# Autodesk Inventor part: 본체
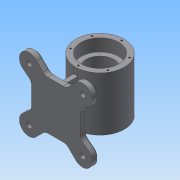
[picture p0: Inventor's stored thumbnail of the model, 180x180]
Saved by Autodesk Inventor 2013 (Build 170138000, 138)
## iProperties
Created: 2018-03
Part Number: 본체
Material: 일반
Document SubType Name: Modeling
Designer: Administrator
Density: 1 g/cm^3
Author: Administrator
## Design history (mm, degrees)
sketch "스케치2"
  geometry: C1 r 45 at (0, 0); 1 further point
  constraints: 1 centre point, 1 coincident
  dimensions: "d42" = 90 diameter of C1
extrude "돌출2" new body sketch "스케치2" stored distance "d44" = 100; taper "d45" = 0 deg
hole "구멍1" diameter "d48" = 70; stored, may be unused: countersink angle "d52" = 90 deg, drill point angle "d54" = 0 deg; dims "d46" = 10, "d47" = 10, "d49" = 6, "d50" = 4, "d51" = 2, "d53" = 23
hole "구멍2" diameter "d57" = 52; stored, may be unused: countersink angle "d61" = 90 deg, drill point angle "d63" = 0 deg; dims "d55" = 10, "d56" = 10, "d58" = 6, "d59" = 4, "d60" = 2, "d62" = 47
hole "구멍3" diameter "d66" = 40; stored, may be unused: countersink angle "d70" = 90 deg, drill point angle "d72" = 0 deg; dims "d64" = 10, "d65" = 10, "d67" = 6, "d68" = 4, "d69" = 2, "d71" = 30
node "작업 평면2"
sketch "스케치4"
  geometry: L1 (0, 0)-(-45, 0); L2 (-45, 0)-(-45, 45); L3 (-45, 45)-(0, 45); L4 (0, 45)-(0, 0); L5 (0, 0)-(-49.497, 49.497); L6 (0, 0)-(70, 0); L7 (-60.483, 35.239)-(-49.871, 27.062); L8 (-35.239, 60.483)-(-23.417, 48.661); L9 (0, 45)-(-14.578, 45); L10 (-45, 0)-(-45, 17.16); A1 r 70 centre (0, 0) between (-49.497, 49.497) and (-60.483, 35.239); A2 r 18 centre (-49.497, 49.497) between (-35.239, 60.483) and (-60.483, 35.239); A3 r 12.5 centre (-57.5, 17.16) between (-45, 17.16) and (-49.871, 27.062); A4 r 12.5 centre (-14.578, 57.5) between (-23.417, 48.661) and (-14.578, 45)
  constraints: 20 end point, 9 point on circle, 6 tangent, 4 centre point, 3 parallel, 2 coincident, 2 horizontal, 2 point on line, 1 collinear, 1 equal length, 1 perpendicular
  dimensions: "d74" = 45 distance of L2.end L3.end; "d75" = 45 distance of L1.end L2.end; "d76" = 140 diameter of A1; "d77" = 135 deg angle of L6 L5; "d78" = 36 diameter of A2; "d79" = 25 diameter of A3; "d80" = 25 diameter of A4
extrude "돌출3" join sketch "스케치4" distance "d81" = 12; taper "d82" = 0 deg
sketch "스케치5"
  geometry: L1 (-45, -82)-(-45, -70) reference; L2 (-45, -70)-(45, -70) reference; L3 (45, -70)-(45, -82) reference; L4 (45, -82)-(-45, -82) reference; L5 (21.342, -39.617)-(24, -70); L6 (-21.342, -39.617)-(-24, -70); L7 (-24, -70)-(0, -70); L8 (0, -70)-(24, -70); C1 r 26 at (0, 0) reference; A1 r 45 centre (0, 0) between (21.342, -39.617) and (-21.342, -39.617) reference; 1 further point
  constraints: 8 end point, 2 point on circle, 2 point on line, 1 collinear, 1 midpoint
  dimensions: "d85" = 24 distance of L6.end L7.end; "d86" = 24 distance of L5.end L7.end; "d87" = 95 deg angle of L5 L2; "d88" = 95 deg angle of L2 L6
extrude "돌출4" join sketch "스케치5" stored distance "d89" = 8; taper "d90" = 0 deg
sketch "스케치6"
  geometry: L1 (35, 27)-(35, 50) reference; L2 (35, 50)-(45, 50) reference; L3 (45, 50)-(45, -50) reference; L4 (45, -50)-(20, -50) reference; L5 (20, -50)-(20, -20) reference; L6 (20, -20)-(26, -20) reference; L7 (26, -20)-(26, 27) reference; L8 (26, 27)-(35, 27) reference; L9 (-82, 45)-(-70, 45) reference; L10 (-70, 45)-(-70, 4) reference; L11 (-70, 4)-(-45, 4) reference; L12 (-45, 4)-(-45, 50) reference; L13 (-45, 50)-(-35, 50) reference; L14 (-35, 50)-(-35, 27) reference; L15 (-35, 27)-(-26, 27) reference; L16 (-26, 27)-(-26, -20) reference; L17 (-26, -20)-(-20, -20) reference; L18 (-20, -20)-(-20, -50) reference; L19 (-20, -50)-(-45, -50) reference; L20 (-45, -50)-(-45, -4) reference; L21 (-45, -4)-(-70, -4) reference; L22 (-70, -4)-(-70, -45) reference; L23 (-70, -45)-(-82, -45) reference; L24 (-82, -45)-(-82, 45) reference; L25 (-70, 4)-(-70, -4); L26 (-70, 0)-(-70, 37); L27 (-70, 0)-(-70, -37); L28 (-70, 37)-(-45, 37); L29 (-70, -37)-(-45, -37); 1 further point
  constraints: 10 end point, 4 point on line, 2 perpendicular, 1 midpoint, 1 parallel
  dimensions: "d93" = 37 distance of L26.start L26.end; "d94" = 37 distance of L26.start L27.end
extrude "돌출5" join sketch "스케치6" stored distance "d95" = 8; taper "d96" = 0 deg
sketch "스케치7"
  geometry: A1 r 45 centre (0, 0) between (4, -44.822) and (-4, -44.822) reference; 1 further point
  constraints: 1 vertical alignment
  dimensions: "d97" = 40 distance of A1.centre point (0, 40)
hole "구멍4" sketch "스케치7" at (0, 40) diameter "d98" = 3.242; stored, may be unused: countersink angle "d102" = 90 deg, drill point angle "d104" = 118 deg; dims "d99" = 9, "d100" = 4, "d101" = 2, "d103" = 11
node "작업 평면3"
sketch "스케치8"
  geometry: L1 (-12.5, -12.5)-(12.5, -12.5); L2 (12.5, -12.5)-(12.5, 12.5); L3 (12.5, 12.5)-(-12.5, 12.5); L4 (-12.5, 12.5)-(-12.5, -12.5); L5 (-12.5, -12.5)-(12.5, 12.5); L6 (12.5, -12.5)-(-12.5, 12.5); 1 further point
  constraints: 12 end point, 2 midpoint, 2 parallel, 1 horizontal, 1 perpendicular
  dimensions: "d108" = 25 distance of L3.end L2.end; "d109" = 25 distance of L2.end L1.end
extrude "돌출6" join sketch "스케치8" stored distance "d110" = 8; taper "d111" = 0 deg
sketch "스케치9"
  geometry: L1 (-7.5, -7.5)-(7.5, -7.5); L2 (7.5, -7.5)-(7.5, 7.5); L3 (7.5, 7.5)-(-7.5, 7.5); L4 (-7.5, 7.5)-(-7.5, -7.5); L5 (-7.5, -7.5)-(7.5, 7.5); L6 (7.5, -7.5)-(-7.5, 7.5); 1 further point
  constraints: 12 end point, 2 midpoint, 2 parallel, 1 horizontal, 1 perpendicular
  dimensions: "d112" = 15 distance of L3.end L2.end; "d113" = 15 distance of L2.end L1.end
extrude "돌출7" cut sketch "스케치9" stored distance "d114" = 8; taper "d115" = 0 deg
sketch "스케치10"
  geometry: C1 r 5 at (49.497, 49.497); C2 r 5 at (-49.497, 49.497); C3 r 5 at (-49.497, -49.497); C4 r 5 at (49.497, -49.497); A1 r 18 centre (49.497, 49.497) between (60.483, 35.239) and (35.239, 60.483) reference; A2 r 18 centre (49.497, -49.497) between (35.239, -60.483) and (60.483, -35.239) reference; A3 r 18 centre (-49.497, 49.497) between (-35.239, 60.483) and (-60.483, 35.239) reference; A4 r 18 centre (-49.497, -49.497) between (-60.483, -35.239) and (-35.239, -60.483) reference; 1 further point
  constraints: 4 centre point, 4 coincident
  dimensions: "d116" = 10 diameter of C1; "d122" = 5 radius of C2; "d123" = 5 radius of C3; "d124" = 5 radius of C4
extrude "돌출8" cut sketch "스케치10" stored distance "d119" = 8; taper "d120" = 0 deg
chamfer "모따기1" distance "d125" = 3; stored, may be unused: second distance "d126" = 2, angle "d127" = 45 deg
node "솔리드2"
mirror "대칭3"
mirror "대칭4"
pattern_circular "원형 패턴1" dims angle "d106" = 360 deg
node "절단 모서리 투영1"
node "절단 모서리 투영2"
other parameters: "d73" = -82
